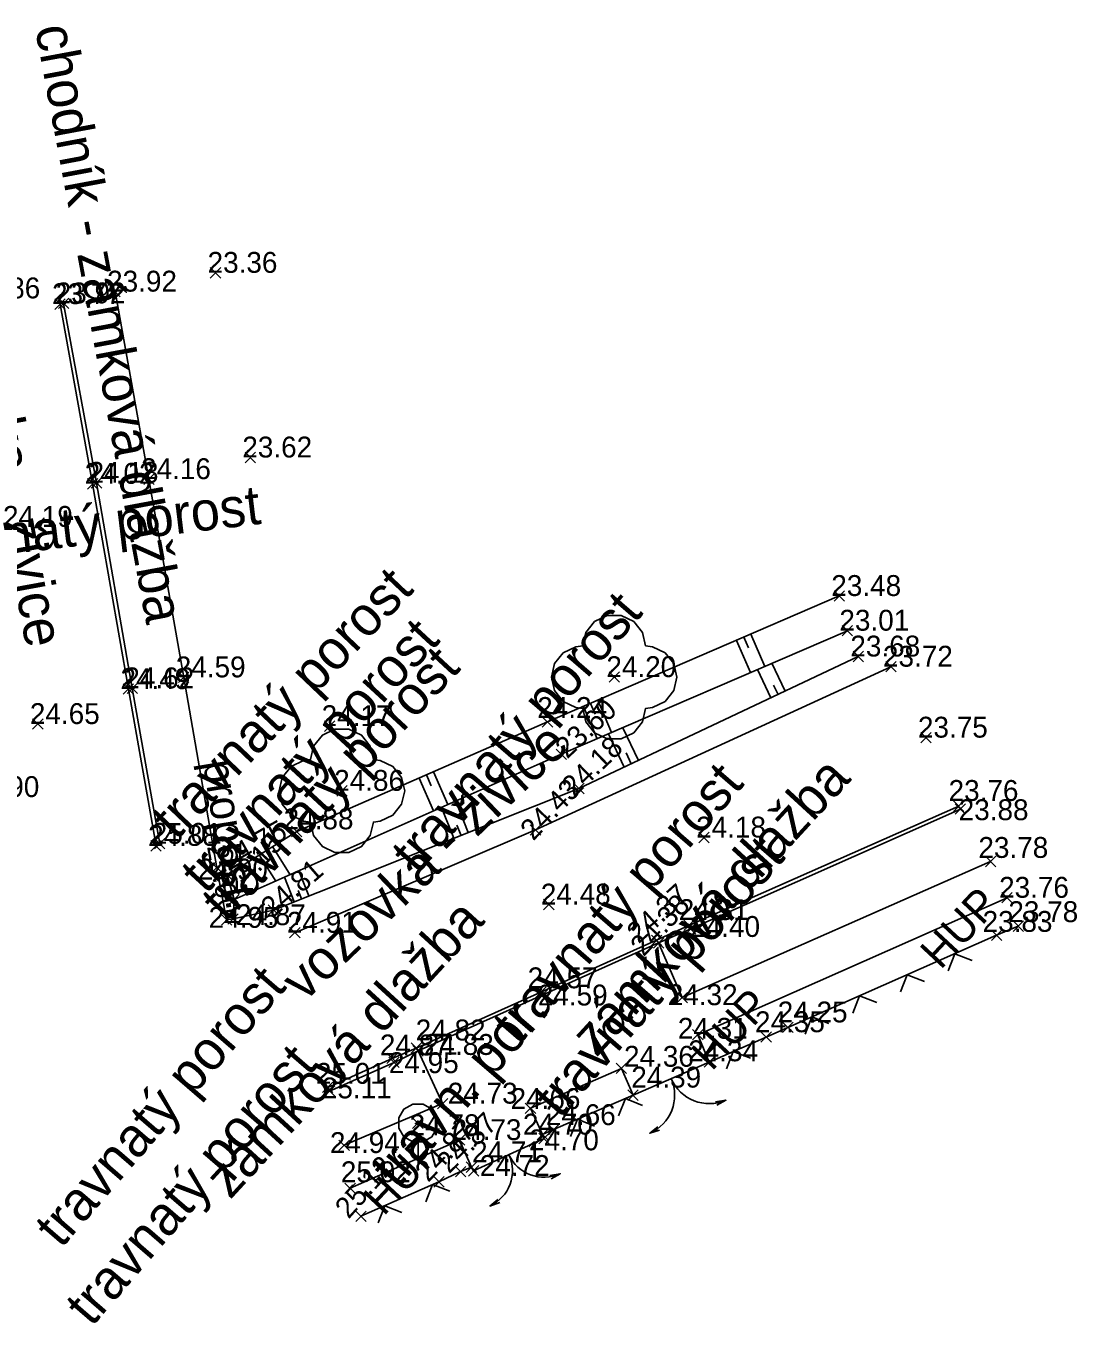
# Model space of a CAD drawing. Extents: x -772278.2 to -772217.5, y -1034079.2 to -1034029.4.
# Drawn here: x -772257.74 to -772217.47, y -1034079.19 to -1034029.39 of the extents above; entities that cross this region are included whole.
import ezdxf

# ---------------------------------------------------------------- set-up
doc = ezdxf.new("R2010")
doc.units = 0
for name, color, linetype in [('Level 13', 7, 'Continuous'), ('Level 16', 7, 'Continuous'), ('Level 24', 7, 'Continuous'), ('Level 32', 7, 'Continuous'), ('Level 33', 7, 'Continuous'), ('Level 34', 7, 'Continuous'), ('Level 35', 7, 'Continuous'), ('Level 36', 7, 'Continuous'), ('Level 37', 7, 'Continuous'), ('Level 38', 7, 'Continuous'), ('Level 44', 7, 'Continuous')]:
    doc.layers.add(name, color=color, linetype=linetype)

msp = doc.modelspace()

# ---------------------------------------------------------------- linework, layer by layer
at = {"layer": 'Level 13'}
msp.add_line((-772242.77, -1034071.45), (-772242.67, -1034071.45), dxfattribs=at)
msp.add_lwpolyline([(-772242.73, -1034072.17), (-772242.92, -1034072.17), (-772243.26, -1034071.98), (-772243.45, -1034071.64), (-772243.45, -1034071.25), (-772243.26, -1034070.91), (-772242.92, -1034070.72), (-772242.53, -1034070.72), (-772242.19, -1034070.91), (-772242, -1034071.25), (-772242, -1034071.64), (-772242.19, -1034071.98), (-772242.53, -1034072.17), (-772242.72, -1034072.17), (-772242.72, -1034073.2)], dxfattribs=at)
at = {"layer": 'Level 16'}
for p, q in [((-772250.28, -1034039.05), (-772250.68, -1034038.65)), ((-772250.68, -1034039.05), (-772250.28, -1034038.65)), ((-772254.13, -1034039.77), (-772254.53, -1034039.37)), ((-772254.53, -1034039.77), (-772254.13, -1034039.37)), ((-772256.24, -1034040.25), (-772256.64, -1034039.85)), ((-772256.64, -1034040.25), (-772256.24, -1034039.85)), ((-772256.1, -1034040.22), (-772256.5, -1034039.82)), ((-772256.5, -1034040.22), (-772256.1, -1034039.82)), ((-772248.95, -1034046.13), (-772249.35, -1034045.73)), ((-772249.35, -1034046.13), (-772248.95, -1034045.73)), ((-772254.84, -1034047.1), (-772255.24, -1034046.7)), ((-772255.24, -1034047.1), (-772254.84, -1034046.7)), ((-772252.83, -1034046.96), (-772253.23, -1034046.56)), ((-772253.23, -1034046.96), (-772252.83, -1034046.56)), ((-772254.99, -1034047.14), (-772255.39, -1034046.74)), ((-772255.39, -1034047.14), (-772254.99, -1034046.74)), ((-772226.38, -1034051.44), (-772226.78, -1034051.04)), ((-772226.78, -1034051.44), (-772226.38, -1034051.04)), ((-772226.07, -1034052.77), (-772226.47, -1034052.37)), ((-772226.47, -1034052.77), (-772226.07, -1034052.37)), ((-772225.65, -1034053.76), (-772226.05, -1034053.36)), ((-772226.05, -1034053.76), (-772225.65, -1034053.36)), ((-772251.5, -1034054.56), (-772251.9, -1034054.16)), ((-772251.9, -1034054.56), (-772251.5, -1034054.16)), ((-772235, -1034054.55), (-772235.4, -1034054.15)), ((-772235.4, -1034054.55), (-772235, -1034054.15)), ((-772224.4, -1034054.15), (-772224.8, -1034053.75)), ((-772224.8, -1034054.15), (-772224.4, -1034053.75)), ((-772253.62, -1034055.01), (-772254.02, -1034054.61)), ((-772254.02, -1034055.01), (-772253.62, -1034054.61)), ((-772253.47, -1034054.98), (-772253.87, -1034054.58)), ((-772253.87, -1034054.98), (-772253.47, -1034054.58)), ((-772257.09, -1034056.35), (-772257.49, -1034055.95)), ((-772257.49, -1034056.35), (-772257.09, -1034055.95)), ((-772245.91, -1034056.43), (-772246.31, -1034056.03)), ((-772246.31, -1034056.43), (-772245.91, -1034056.03)), ((-772237.56, -1034056.27), (-772237.96, -1034055.87)), ((-772237.96, -1034056.27), (-772237.56, -1034055.87)), ((-772223.06, -1034056.87), (-772223.46, -1034056.47)), ((-772223.46, -1034056.87), (-772223.06, -1034056.47)), ((-772237.03, -1034057.51), (-772237.43, -1034057.11)), ((-772237.43, -1034057.51), (-772237.03, -1034057.11)), ((-772245.43, -1034058.91), (-772245.83, -1034058.51)), ((-772245.83, -1034058.91), (-772245.43, -1034058.51)), ((-772236.36, -1034058.82), (-772236.76, -1034058.42)), ((-772236.76, -1034058.82), (-772236.36, -1034058.42)), ((-772221.8, -1034059.5), (-772222.2, -1034059.1)), ((-772222.2, -1034059.5), (-772221.8, -1034059.1)), ((-772221.74, -1034059.61), (-772222.14, -1034059.21)), ((-772222.14, -1034059.61), (-772221.74, -1034059.21)), ((-772247.17, -1034060.47), (-772247.57, -1034060.07)), ((-772247.57, -1034060.47), (-772247.17, -1034060.07)), ((-772238.02, -1034060.41), (-772238.42, -1034060.01)), ((-772238.42, -1034060.41), (-772238.02, -1034060.01)), ((-772252.56, -1034061.02), (-772252.96, -1034060.62)), ((-772252.96, -1034061.02), (-772252.56, -1034060.62)), ((-772252.42, -1034060.94), (-772252.82, -1034060.54)), ((-772252.82, -1034060.94), (-772252.42, -1034060.54)), ((-772231.56, -1034060.7), (-772231.96, -1034060.3)), ((-772231.96, -1034060.7), (-772231.56, -1034060.3)), ((-772250.23, -1034061.86), (-772250.63, -1034061.46)), ((-772250.63, -1034061.86), (-772250.23, -1034061.46)), ((-772220.58, -1034061.62), (-772220.98, -1034061.22)), ((-772220.98, -1034061.62), (-772220.58, -1034061.22)), ((-772250.177, -1034062.146), (-772250.577, -1034061.746)), ((-772250.577, -1034062.146), (-772250.177, -1034061.746)), ((-772249.83, -1034062.14), (-772250.23, -1034061.74)), ((-772250.23, -1034062.14), (-772249.83, -1034061.74)), ((-772219.95, -1034063.01), (-772220.35, -1034062.61)), ((-772220.35, -1034063.01), (-772219.95, -1034062.61)), ((-772249.57, -1034063.08), (-772249.97, -1034062.68)), ((-772249.97, -1034063.08), (-772249.57, -1034062.68)), ((-772248.06, -1034063.48), (-772248.46, -1034063.08)), ((-772248.46, -1034063.48), (-772248.06, -1034063.08)), ((-772237.51, -1034063.27), (-772237.91, -1034062.87)), ((-772237.91, -1034063.27), (-772237.51, -1034062.87)), ((-772249.857, -1034063.856), (-772250.257, -1034063.456)), ((-772250.257, -1034063.856), (-772249.857, -1034063.456)), ((-772249.61, -1034063.82), (-772250.01, -1034063.42)), ((-772250.01, -1034063.82), (-772249.61, -1034063.42)), ((-772247.24, -1034064.35), (-772247.64, -1034063.95)), ((-772247.64, -1034064.35), (-772247.24, -1034063.95)), ((-772232.14, -1034064.07), (-772232.54, -1034063.67)), ((-772232.54, -1034064.07), (-772232.14, -1034063.67)), ((-772232.07, -1034064.2), (-772232.47, -1034063.8)), ((-772232.47, -1034064.2), (-772232.07, -1034063.8)), ((-772220.35, -1034064.45), (-772220.75, -1034064.05)), ((-772220.75, -1034064.45), (-772220.35, -1034064.05)), ((-772219.52, -1034064.1), (-772219.92, -1034063.7)), ((-772219.92, -1034064.1), (-772219.52, -1034063.7)), ((-772233.38, -1034064.64), (-772233.78, -1034064.24)), ((-772233.78, -1034064.64), (-772233.38, -1034064.24)), ((-772233.3, -1034064.74), (-772233.7, -1034064.34)), ((-772233.7, -1034064.74), (-772233.3, -1034064.34)), ((-772237.81, -1034066.63), (-772238.21, -1034066.23)), ((-772238.21, -1034066.63), (-772237.81, -1034066.23)), ((-772237.76, -1034066.74), (-772238.16, -1034066.34)), ((-772238.16, -1034066.74), (-772237.76, -1034066.34)), ((-772232.4, -1034066.84), (-772232.8, -1034066.44)), ((-772232.8, -1034066.84), (-772232.4, -1034066.44)), ((-772228.35, -1034067.98), (-772228.75, -1034067.58)), ((-772228.75, -1034067.98), (-772228.35, -1034067.58)), ((-772231.8, -1034068.26), (-772232.2, -1034067.86)), ((-772232.2, -1034068.26), (-772231.8, -1034067.86)), ((-772229.18, -1034068.35), (-772229.58, -1034067.95)), ((-772229.58, -1034068.35), (-772229.18, -1034067.95)), ((-772242.59, -1034068.77), (-772242.99, -1034068.37)), ((-772242.99, -1034068.77), (-772242.59, -1034068.37)), ((-772242.52, -1034068.88), (-772242.92, -1034068.48)), ((-772242.92, -1034068.88), (-772242.52, -1034068.48)), ((-772243.51, -1034069.17), (-772243.91, -1034068.77)), ((-772243.91, -1034069.17), (-772243.51, -1034068.77)), ((-772243.44, -1034069.32), (-772243.84, -1034068.92)), ((-772243.84, -1034069.32), (-772243.44, -1034068.92)), ((-772231.36, -1034069.31), (-772231.76, -1034068.91)), ((-772231.76, -1034069.31), (-772231.36, -1034068.91)), ((-772234.73, -1034069.55), (-772235.13, -1034069.15)), ((-772235.13, -1034069.55), (-772234.73, -1034069.15)), ((-772245.98, -1034070.28), (-772246.38, -1034069.88)), ((-772246.38, -1034070.28), (-772245.98, -1034069.88)), ((-772245.91, -1034070.42), (-772246.31, -1034070.02)), ((-772246.31, -1034070.42), (-772245.91, -1034070.02)), ((-772241.58, -1034070.9), (-772241.98, -1034070.5)), ((-772241.98, -1034070.9), (-772241.58, -1034070.5)), ((-772234.28, -1034070.58), (-772234.68, -1034070.18)), ((-772234.68, -1034070.58), (-772234.28, -1034070.18)), ((-772238.21, -1034071.08), (-772238.61, -1034070.68)), ((-772238.61, -1034071.08), (-772238.21, -1034070.68)), ((-772242.53, -1034071.65), (-772242.93, -1034071.25)), ((-772242.93, -1034071.65), (-772242.53, -1034071.25)), ((-772237.33, -1034071.9), (-772237.73, -1034071.5)), ((-772237.73, -1034071.9), (-772237.33, -1034071.5)), ((-772245.35, -1034072.5), (-772245.75, -1034072.1)), ((-772245.75, -1034072.5), (-772245.35, -1034072.1)), ((-772240.93, -1034072.3), (-772241.33, -1034071.9)), ((-772241.33, -1034072.3), (-772240.93, -1034071.9)), ((-772237.75, -1034072.09), (-772238.15, -1034071.69)), ((-772238.15, -1034072.09), (-772237.75, -1034071.69)), ((-772237.69, -1034072.24), (-772238.09, -1034071.84)), ((-772238.09, -1034072.24), (-772237.69, -1034071.84)), ((-772240.47, -1034073.34), (-772240.87, -1034072.94)), ((-772240.87, -1034073.34), (-772240.47, -1034072.94)), ((-772240.39, -1034073.48), (-772240.79, -1034073.08)), ((-772240.79, -1034073.48), (-772240.39, -1034073.08)), ((-772241.72, -1034073.9), (-772242.12, -1034073.5)), ((-772242.12, -1034073.9), (-772241.72, -1034073.5)), ((-772240.89, -1034073.51), (-772241.29, -1034073.11)), ((-772241.29, -1034073.51), (-772240.89, -1034073.11)), ((-772245.12, -1034074.15), (-772245.52, -1034073.75)), ((-772245.52, -1034074.15), (-772245.12, -1034073.75)), ((-772244.71, -1034075.22), (-772245.11, -1034074.82)), ((-772245.11, -1034075.22), (-772244.71, -1034074.82))]:
    msp.add_line(p, q, dxfattribs=at)
at = {"layer": 'Level 24'}
for p, q in [((-772220.55, -1034064.25), (-772219.72, -1034063.9)), ((-772229.38, -1034068.15), (-772228.55, -1034067.78)), ((-772241.92, -1034073.7), (-772241.09, -1034073.31))]:
    msp.add_line(p, q, dxfattribs=at)
at = {"layer": 'Level 32'}
for p, q in [((-772224.6, -1034053.95), (-772238.22, -1034060.21)), ((-772251.7, -1034054.36), (-772250.43, -1034061.66)), ((-772253.82, -1034054.81), (-772252.76, -1034060.82)), ((-772253.67, -1034054.78), (-772252.62, -1034060.74)), ((-772247.44, -1034064.15), (-772238.22, -1034060.21)), ((-772246.18, -1034070.08), (-772243.71, -1034068.97)), ((-772246.11, -1034070.22), (-772243.64, -1034069.12)), ((-772245.55, -1034072.3), (-772241.78, -1034070.7)), ((-772245.32, -1034073.95), (-772241.13, -1034072.1)), ((-772241.13, -1034072.1), (-772240.67, -1034073.14))]:
    msp.add_line(p, q, dxfattribs=at)
for points in [[(-772251.7, -1034054.36), (-772253.03, -1034046.76), (-772254.33, -1034039.57)], [(-772253.82, -1034054.81), (-772255.19, -1034046.94), (-772256.44, -1034040.05)], [(-772253.67, -1034054.78), (-772255.04, -1034046.9), (-772256.3, -1034040.02)], [(-772243.71, -1034068.97), (-772242.79, -1034068.57), (-772238.01, -1034066.43), (-772233.58, -1034064.44), (-772232.34, -1034063.87), (-772222, -1034059.3)], [(-772233.5, -1034064.54), (-772232.27, -1034064), (-772221.94, -1034059.41)], [(-772242.72, -1034068.68), (-772237.96, -1034066.54), (-772233.5, -1034064.54), (-772232.6, -1034066.64), (-772220.78, -1034061.42)], [(-772231.56, -1034069.11), (-772232, -1034068.06), (-772220.15, -1034062.81)], [(-772243.64, -1034069.12), (-772242.72, -1034068.68), (-772241.78, -1034070.7)], [(-772237.95, -1034071.89), (-772238.41, -1034070.88), (-772234.93, -1034069.35), (-772234.48, -1034070.38)]]:
    msp.add_lwpolyline(points, dxfattribs=at)
at = {"layer": 'Level 33'}
for points in [[(-772226.58, -1034051.24), (-772237.76, -1034056.07), (-772247.37, -1034060.27), (-772250.03, -1034061.94)], [(-772226.27, -1034052.57), (-772237.23, -1034057.31), (-772249.77, -1034062.88)], [(-772225.85, -1034053.56), (-772236.56, -1034058.62), (-772248.26, -1034063.28), (-772249.81, -1034063.62)]]:
    msp.add_lwpolyline(points, dxfattribs=at)
at = {"layer": 'Level 34'}
for p, q in [((-772228.55, -1034067.78), (-772220.55, -1034064.25)), ((-772231.56, -1034069.11), (-772229.38, -1034068.15)), ((-772231.56, -1034069.11), (-772234.48, -1034070.38)), ((-772237.53, -1034071.7), (-772234.48, -1034070.38)), ((-772237.89, -1034072.04), (-772240.59, -1034073.28)), ((-772244.91, -1034075.02), (-772241.92, -1034073.7))]:
    msp.add_line(p, q, dxfattribs=at)
for points in [[(-772222.401, -1034065.614), (-772222.146, -1034064.954), (-772221.486, -1034065.209)], [(-772224.231, -1034066.421), (-772223.976, -1034065.762), (-772223.316, -1034066.017)], [(-772226.061, -1034067.228), (-772225.805, -1034066.569), (-772225.146, -1034066.824)], [(-772227.89, -1034068.036), (-772227.635, -1034067.376), (-772226.976, -1034067.632)], [(-772230.901, -1034069.366), (-772230.645, -1034068.707), (-772229.986, -1034068.963)], [(-772235.037, -1034071.166), (-772234.777, -1034070.508), (-772234.119, -1034070.769)], [(-772231.275, -1034070.766), (-772230.926, -1034070.571), (-772231.321, -1034070.635)], [(-772236.873, -1034071.96), (-772236.612, -1034071.303), (-772235.955, -1034071.563)], [(-772233.528, -1034071.594), (-772233.844, -1034071.839), (-772233.463, -1034071.717)], [(-772237.89, -1034072.04), (-772237.95, -1034071.89), (-772237.53, -1034071.7)], [(-772241.09, -1034073.31), (-772240.67, -1034073.14), (-772240.59, -1034073.28)], [(-772237.617, -1034073.591), (-772237.271, -1034073.39), (-772237.665, -1034073.461)], [(-772242.421, -1034074.468), (-772242.166, -1034073.808), (-772241.506, -1034074.064)], [(-772239.659, -1034074.377), (-772239.969, -1034074.63), (-772239.591, -1034074.498)], [(-772244.25, -1034075.276), (-772243.995, -1034074.616), (-772243.336, -1034074.871)]]:
    msp.add_lwpolyline(points, dxfattribs=at)
for centre, radius, start, end in [((-772234.48, -1034070.38), 1.592, 293.5514, 23.5057), ((-772231.56, -1034069.11), 1.592, 203.5057, 293.4601), ((-772240.59, -1034073.28), 1.486, 294.713, 24.6674), ((-772237.89, -1034072.04), 1.486, 204.6674, 294.6218)]:
    msp.add_arc(centre, radius, start, end, dxfattribs=at)
at = {"layer": 'Level 35'}
for points in [[(-772232.8, -1034054.35), (-772232.92, -1034054.866), (-772233.256, -1034055.286), (-772233.736, -1034055.514), (-772234, -1034055.55), (-772234.12, -1034056.066), (-772234.456, -1034056.486), (-772234.936, -1034056.714), (-772235.476, -1034056.714), (-772235.956, -1034056.486), (-772236.292, -1034056.066), (-772236.412, -1034055.55), (-772236.676, -1034055.514), (-772237.156, -1034055.286), (-772237.492, -1034054.866), (-772237.612, -1034054.35), (-772237.492, -1034053.834), (-772237.156, -1034053.414), (-772236.676, -1034053.186), (-772236.412, -1034053.15), (-772236.292, -1034052.634), (-772235.956, -1034052.214), (-772235.476, -1034051.986), (-772234.936, -1034051.986), (-772234.456, -1034052.214), (-772234.12, -1034052.634), (-772234, -1034053.15), (-772233.736, -1034053.186), (-772233.256, -1034053.414), (-772232.92, -1034053.834)], [(-772243.23, -1034058.71), (-772243.35, -1034059.226), (-772243.686, -1034059.646), (-772244.166, -1034059.874), (-772244.43, -1034059.91), (-772244.55, -1034060.426), (-772244.886, -1034060.846), (-772245.366, -1034061.074), (-772245.906, -1034061.074), (-772246.386, -1034060.846), (-772246.722, -1034060.426), (-772246.842, -1034059.91), (-772247.106, -1034059.874), (-772247.586, -1034059.646), (-772247.922, -1034059.226), (-772248.042, -1034058.71), (-772247.922, -1034058.194), (-772247.586, -1034057.774), (-772247.106, -1034057.546), (-772246.842, -1034057.51), (-772246.722, -1034056.994), (-772246.386, -1034056.574), (-772245.906, -1034056.346), (-772245.366, -1034056.346), (-772244.886, -1034056.574), (-772244.55, -1034056.994), (-772244.43, -1034057.51), (-772244.166, -1034057.546), (-772243.686, -1034057.774), (-772243.35, -1034058.194)]]:
    msp.add_lwpolyline(points, close=True, dxfattribs=at)
for points in [[(-772235.26, -1034054.35), (-772235.2, -1034054.35), (-772235.14, -1034054.35)], [(-772245.69, -1034058.71), (-772245.63, -1034058.71), (-772245.57, -1034058.71)]]:
    msp.add_lwpolyline(points, dxfattribs=at)
at = {"layer": 'Level 38'}
for p, q in [((-772230.516, -1034052.941), (-772229.983, -1034054.176)), ((-772230.241, -1034052.822), (-772230.063, -1034053.233)), ((-772229.966, -1034052.703), (-772229.432, -1034053.938)), ((-772229.197, -1034055.141), (-772229.709, -1034054.057)), ((-772228.654, -1034054.885), (-772229.158, -1034053.819)), ((-772228.925, -1034055.013), (-772229.094, -1034054.655)), ((-772236.386, -1034055.476), (-772235.851, -1034056.714)), ((-772236.11, -1034055.357), (-772235.932, -1034055.769)), ((-772235.835, -1034055.238), (-772235.301, -1034056.476)), ((-772234.82, -1034057.798), (-772235.42, -1034056.527)), ((-772234.277, -1034057.542), (-772234.869, -1034056.289)), ((-772234.549, -1034057.67), (-772234.747, -1034057.25)), ((-772242.401, -1034058.098), (-772242.217, -1034058.519)), ((-772242.126, -1034057.978), (-772241.575, -1034059.24)), ((-772242.676, -1034058.219), (-772242.123, -1034059.483)), ((-772240.794, -1034060.306), (-772241.272, -1034059.105)), ((-772241.351, -1034060.528), (-772241.821, -1034059.349)), ((-772241.073, -1034060.417), (-772241.23, -1034060.021)), ((-772248.548, -1034061.01), (-772248.331, -1034061.355)), ((-772248.294, -1034060.85), (-772247.619, -1034061.925)), ((-772248.802, -1034061.169), (-772248.173, -1034062.171)), ((-772247.463, -1034062.963), (-772247.838, -1034062.022)), ((-772246.906, -1034062.741), (-772247.289, -1034061.778)), ((-772247.184, -1034062.852), (-772247.311, -1034062.535))]:
    msp.add_line(p, q, dxfattribs=at)
at = {"layer": 'Level 44'}
msp.add_line((-772250.377, -1034061.946), (-772250.057, -1034063.656), dxfattribs=at)
msp.add_lwpolyline([(-772250.057, -1034063.656), (-772249.81, -1034063.62), (-772249.77, -1034062.88), (-772250.03, -1034061.94), (-772250.377, -1034061.946)], dxfattribs=at)

# ---------------------------------------------------------------- texts
at = {"layer": 'Level 36'}
for s, height, rotation, p in [('chodník - zámková dlažba', 1.5, 280.5774, (-772257.402, -1034029.462)), ('vozovka - živice', 1.5, 280.4055, (-772260.283, -1034039.364)), ('travnatý porost', 1.5, 6.8755, (-772261.868, -1034050.058)), ('travnatý porost', 1.5, 46.4096, (-772251.984, -1034060.642)), ('travnatý porost', 1.5, 49.1598, (-772242.74, -1034061.941)), ('travnatý porost', 1.5, 47.2117, (-772250.846, -1034062.707)), ('travnatý porost', 1.5, 47.2117, (-772250.06, -1034063.778)), ('vozovka - živice', 1.5, 43.774, (-772247.074, -1034066.835)), ('propust.', 1.2, 279.3169, (-772250.978, -1034057.611)), ('travnatý porost', 1.5, 49.1598, (-772238.861, -1034068.496)), ('zámková dlažba', 1.5, 47.4409, (-772235.89, -1034068.956)), ('travnatý porost', 1.5, 49.1598, (-772237.283, -1034071.315)), ('HUP', 1.2, 46.9825, (-772222.698, -1034065.602)), ('zámková dlažba', 1.5, 47.4409, (-772249.921, -1034074.409)), ('travnatý porost', 1.5, 49.1598, (-772256.396, -1034076.286)), ('HUP', 1.2, 46.9825, (-772231.466, -1034069.489)), ('travn. por.', 1.5, 49.389, (-772243.517, -1034074.012)), ('travnatý porost', 1.5, 49.1598, (-772255.227, -1034079.295)), ('HUP', 1.2, 46.9825, (-772244.039, -1034075.046))]:
    msp.add_text(s, height=height, rotation=rotation, dxfattribs=at).set_placement(p)
at = {"layer": 'Level 37'}
for s, p in [('23.36', (-772250.785, -1034038.85)), ('23.86', (-772259.875, -1034039.83)), ('23.77', (-772256.745, -1034040.05)), ('23.92', (-772256.605, -1034040.02)), ('23.92', (-772254.635, -1034039.57)), ('23.62', (-772249.455, -1034045.93)), ('24.02', (-772255.495, -1034046.94)), ('24.18', (-772255.345, -1034046.9)), ('24.16', (-772253.335, -1034046.76)), ('24.19', (-772258.625, -1034048.59)), ('23.48', (-772226.885, -1034051.24)), ('23.01', (-772226.575, -1034052.57)), ('23.68', (-772226.155, -1034053.56)), ('23.72', (-772224.905, -1034053.95)), ('24.59', (-772252.005, -1034054.36)), ('24.20', (-772235.505, -1034054.35)), ('24.49', (-772254.125, -1034054.81)), ('24.62', (-772253.975, -1034054.78)), ('24.24', (-772238.153, -1034055.916)), ('24.65', (-772257.595, -1034056.15)), ('24.17', (-772246.415, -1034056.23)), ('23.75', (-772223.565, -1034056.67)), ('24.90', (-772259.909, -1034058.949)), ('24.86', (-772245.935, -1034058.71)), ('23.76', (-772222.39, -1034059.097)), ('23.88', (-772222.003, -1034059.836)), ('24.88', (-772247.871, -1034060.185)), ('24.88', (-772253.065, -1034060.82)), ('25.01', (-772252.925, -1034060.74)), ('24.18', (-772232.065, -1034060.5)), ('23.78', (-772221.248, -1034061.281)), ('24.90', (-772251.152, -1034062.111)), ('23.76', (-772220.455, -1034062.81)), ('24.48', (-772238.015, -1034063.07)), ('24.87', (-772249.697, -1034063.86)), ('24.31', (-772232.73, -1034063.664)), ('23.78', (-772220.1, -1034063.743)), ('24.95', (-772250.744, -1034063.962)), ('24.91', (-772247.745, -1034064.15)), ('24.40', (-772232.292, -1034064.311)), ('23.83', (-772221.087, -1034064.117)), ('24.57', (-772238.519, -1034066.28)), ('24.59', (-772238.132, -1034066.94)), ('24.32', (-772233.152, -1034066.927)), ('24.25', (-772228.939, -1034067.589)), ('24.82', (-772242.81, -1034068.278)), ('24.31', (-772232.766, -1034068.215)), ('24.35', (-772229.808, -1034067.965)), ('24.87', (-772244.184, -1034068.853)), ('24.83', (-772242.495, -1034068.835)), ('24.36', (-772234.828, -1034069.289)), ('24.34', (-772232.367, -1034069.078)), ('24.95', (-772243.839, -1034069.533)), ('25.01', (-772246.634, -1034069.942)), ('24.39', (-772234.548, -1034070.087)), ('25.11', (-772246.405, -1034070.5)), ('24.73', (-772241.582, -1034070.702)), ('24.66', (-772239.175, -1034070.909)), ('24.78', (-772243.045, -1034071.913)), ('24.70', (-772238.7, -1034071.891)), ('24.66', (-772237.822, -1034071.527)), ('24.73', (-772241.435, -1034072.1)), ('24.94', (-772246.097, -1034072.597)), ('24.70', (-772238.47, -1034072.493)), ('24.71', (-772240.65, -1034072.948)), ('25.02', (-772245.679, -1034073.717)), ('24.72', (-772240.355, -1034073.476))]:
    msp.add_text(s, height=0.8, dxfattribs=at).set_placement(p)
for s, rotation, p in [('23.60', 42.7427, (-772237.008, -1034057.508)), ('24.18', 43.8886, (-772236.74, -1034058.979)), ('24.43', 46.1804, (-772238.305, -1034060.655)), ('24.75', 29.5646, (-772249.992, -1034061.8)), ('24.15', 47.3263, (-772249.635, -1034062.734)), ('25.00', 280.291, (-772250.81, -1034060.846)), ('24.81', 40.9092, (-772248.304, -1034063.623)), ('24.37', 42.0551, (-772234.268, -1034064.596)), ('24.38', 47.0971, (-772234.077, -1034065.1)), ('24.87', 44.4615, (-772241.532, -1034073.415)), ('24.87', 46.5242, (-772242.33, -1034073.749)), ('25.12', 48.1285, (-772245.381, -1034075.151))]:
    msp.add_text(s, height=0.8, rotation=rotation, dxfattribs=at).set_placement(p)

doc.saveas('drawing.dxf')
